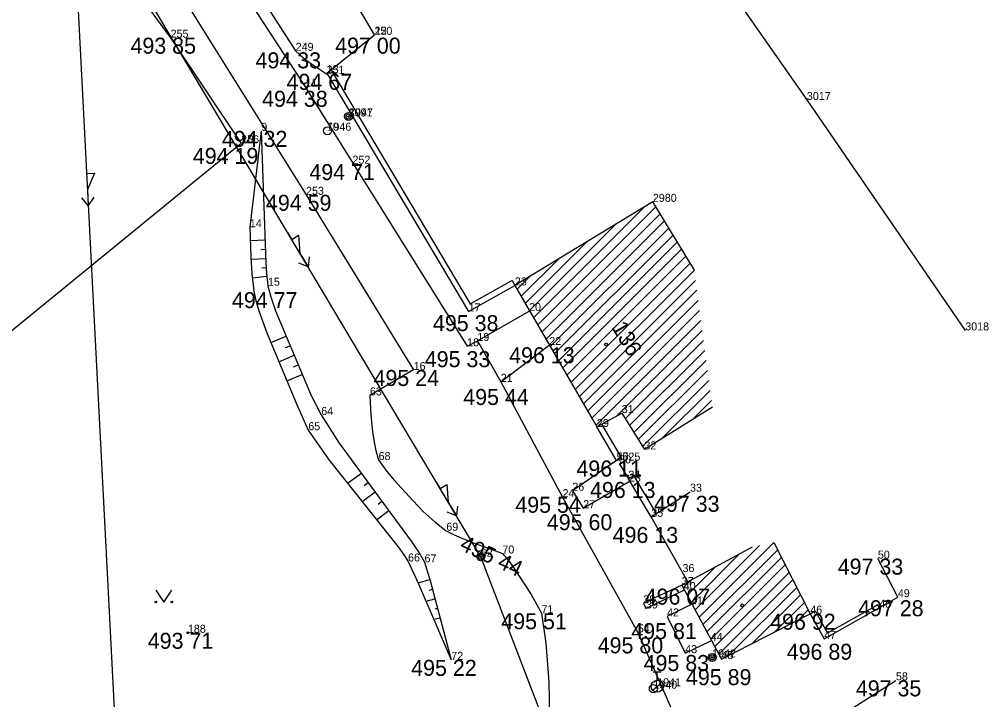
# Model space of a CAD drawing. Extents: x -559180 to -551373, y -1076947 to -1072071.
# Drawn here: x -553435.4 to -553374.8, y -1076636.3 to -1076593.8 of the extents above; entities that cross this region are included whole.
import ezdxf

# ---------------------------------------------------------------- set-up
doc = ezdxf.new("R2010")
doc.units = 0
for name, color, linetype in [('12_PLOTY', 7, 'Continuous'), ('14_BUDOVY', 7, 'Continuous'), ('17_KOMUNIKACE', 7, 'Continuous'), ('18_POLOHOPIS', 7, 'Continuous'), ('1_VODA_ZN', 7, 'Continuous'), ('20_EL_ZN', 7, 'Continuous'), ('26_SRAFY', 7, 'Continuous'), ('27_HRANA_PATA', 7, 'Continuous'), ('32', 7, 'Continuous'), ('3_BODY', 7, 'Continuous'), ('45_ZN_KULTURY', 7, 'Continuous'), ('47_ZN_STAV_OBJ$', 7, 'Continuous'), ('54_C_POPISNA', 7, 'Continuous'), ('6_VYSKY', 7, 'Continuous'), ('NNnadzemní', 7, 'Continuous')]:
    doc.layers.add(name, color=color, linetype=linetype)

# ---------------------------------------------------------------- blocks, each defined once
blk = doc.blocks.new('POINT_DISPLAY')
blk.add_line((0, 0), (0, 0))
blk = doc.blocks.new('SLB')
at = {"layer": '20_EL_ZN'}
for radius in [0.25, 0.158, 0.05]:
    blk.add_circle((0, 0), radius, dxfattribs=at)
blk = doc.blocks.new('BZ')
at = {"layer": '47_ZN_STAV_OBJ$'}
blk.add_circle((0, 0), 0.0875, dxfattribs=at)
blk = doc.blocks.new('PARK')
at = {"layer": '45_ZN_KULTURY'}
for p, q in [((-0.5, 0.75), (0, 0)), ((0, 0), (0.5, 0.75))]:
    blk.add_line(p, q, dxfattribs=at)
for centre in [(-0.5, 0), (0.5, 0)]:
    blk.add_circle(centre, 0.05, dxfattribs=at)
blk = doc.blocks.new('T')
at = {"layer": '6_VYSKY'}
blk.add_circle((0, 0), 0.05, dxfattribs=at)
blk = doc.blocks.new('SV')
at = {"layer": '1_VODA_ZN'}
blk.add_circle((0, 0), 0.25, dxfattribs=at)
blk = doc.blocks.new('OSV')
at = {"layer": '1_VODA_ZN'}
for radius in [0.25, 0.158, 0.05]:
    blk.add_circle((0, 0), radius, dxfattribs=at)
blk = doc.blocks.new('HYP')
at = {"layer": '1_VODA_ZN'}
for p, q in [((-0.25, 0.9), (0.25, 0.9)), ((0, 0.375), (0, 0.9)), ((-0.265, -0.265), (0.265, 0.265))]:
    blk.add_line(p, q, dxfattribs=at)
blk.add_circle((0, 0), 0.375, dxfattribs=at)
blk = doc.blocks.new('ELNN')
at = {"layer": '20_EL_ZN'}
for p, q in [((0, 0), (0.5, 0)), ((0.5, 0), (0.5, 0.5)), ((0.5, 0.5), (1.5, 0)), ((1.5, 0), (2.5, 0))]:
    blk.add_line(p, q, dxfattribs=at)
blk.add_lwpolyline([(2, 0.375), (2.5, 0), (2, -0.375)], dxfattribs=at)

msp = doc.modelspace()

# ---------------------------------------------------------------- linework, layer by layer
at = {"layer": '12_PLOTY'}
for p, q in [((-553413.2, -1076594.75), (-553428.34, -1076568.96)), ((-553397.99, -1076581.92), (-553386.19, -1076598.82)), ((-553428.08, -1076592), (-553425.93, -1076594.93)), ((-553425.93, -1076594.93), (-553421.52, -1076601.53)), ((-553416.18, -1076597.14), (-553413.2, -1076594.75)), ((-553407.193, -1076611.547), (-553415.904, -1076596.918)), ((-553416.18, -1076597.14), (-553407.32, -1076612.02)), ((-553386.19, -1076598.82), (-553376.3, -1076613.21)), ((-553421.52, -1076601.53), (-553438.11, -1076615.08)), ((-553407.32, -1076612.02), (-553404.43, -1076610.4)), ((-553404.601, -1076610.094), (-553407.193, -1076611.547)), ((-553404.601, -1076610.094), (-553404.43, -1076610.4)), ((-553398.08, -1076621.33), (-553399.3, -1076619.24)), ((-553397.777, -1076621.153), (-553398.997, -1076619.063)), ((-553398.08, -1076621.33), (-553397.777, -1076621.153)), ((-553397.91, -1076621.51), (-553397.34, -1076622.47)), ((-553397.34, -1076622.47), (-553396.997, -1076622.263)), ((-553395.91, -1076624.85), (-553397.34, -1076622.47)), ((-553395.574, -1076624.632), (-553396.997, -1076622.263)), ((-553395.91, -1076624.85), (-553393.49, -1076623.28)), ((-553393.621, -1076628.9), (-553395.91, -1076624.85)), ((-553380.51, -1076629.87), (-553381.76, -1076627.46)), ((-553381.768, -1076630.355), (-553384.902, -1076632.122)), ((-553381.67, -1076630.53), (-553381.768, -1076630.355)), ((-553381.67, -1076630.53), (-553380.51, -1076629.87)), ((-553385.98, -1076630.9), (-553385.673, -1076630.73)), ((-553385.98, -1076630.9), (-553385.11, -1076632.47)), ((-553385.673, -1076630.73), (-553384.902, -1076632.122)), ((-553385.11, -1076632.47), (-553381.67, -1076630.53))]:
    msp.add_line(p, q, dxfattribs=at)
at = {"layer": '14_BUDOVY'}
for p, q in [((-553395.81, -1076605.18), (-553404.43, -1076610.4)), ((-553393.22, -1076609.457), (-553395.81, -1076605.18)), ((-553404.43, -1076610.4), (-553399.3, -1076619.24)), ((-553392.093, -1076618.002), (-553396.34, -1076620.64)), ((-553399.3, -1076619.24), (-553397.75, -1076618.37)), ((-553397.75, -1076618.37), (-553396.34, -1076620.64)), ((-553389.609, -1076626.738), (-553394.01, -1076629.11)), ((-553388.255, -1076626.447), (-553385.98, -1076630.9)), ((-553394.01, -1076629.11), (-553391.52, -1076633.73)), ((-553391.52, -1076633.73), (-553385.98, -1076630.9))]:
    msp.add_line(p, q, dxfattribs=at)
at = {"layer": '17_KOMUNIKACE'}
for p, q in [((-553428.17, -1076581.72), (-553417.52, -1076597.99)), ((-553430.75, -1076583.45), (-553417.47, -1076604.74)), ((-553417.52, -1076597.99), (-553407.41, -1076614.2)), ((-553417.47, -1076604.74), (-553410.75, -1076615.68)), ((-553407.41, -1076614.2), (-553406.77, -1076613.87)), ((-553410.75, -1076615.68), (-553413.48, -1076617.27)), ((-553405.31, -1076616.42), (-553401.45, -1076623.62)), ((-553398.08, -1076621.34), (-553400.84, -1076623.22)), ((-553400.16, -1076624.31), (-553397.3, -1076622.65)), ((-553401.45, -1076623.62), (-553396.75, -1076632.07)), ((-553400.84, -1076623.22), (-553400.16, -1076624.31)), ((-553396.75, -1076632.07), (-553393.1, -1076640.32)), ((-553387.89, -1076639.66), (-553380.63, -1076635.06))]:
    msp.add_line(p, q, dxfattribs=at)
for points in [[(-553413.48, -1076617.27), (-553413.422, -1076618.481), (-553413.312, -1076619.549), (-553413.24, -1076620.071), (-553413.127, -1076620.625), (-553413.045, -1076620.945), (-553412.94, -1076621.3)], [(-553412.94, -1076621.3), (-553412.495, -1076621.933), (-553411.99, -1076622.542), (-553410.788, -1076623.858), (-553410.154, -1076624.515), (-553409.404, -1076625.19), (-553408.71, -1076625.72)], [(-553408.71, -1076625.72), (-553408.261, -1076625.962), (-553407.734, -1076626.179), (-553406.798, -1076626.565), (-553405.915, -1076626.869), (-553405.21, -1076627.14)], [(-553405.21, -1076627.14), (-553404.93, -1076627.452), (-553404.608, -1076627.895), (-553403.42, -1076629.704), (-553402.77, -1076630.87)], [(-553402.77, -1076630.87), (-553402.499, -1076632.736), (-553402.307, -1076635.159), (-553402.262, -1076637.403), (-553402.299, -1076638.629), (-553402.4, -1076639.7)]]:
    msp.add_lwpolyline(points, dxfattribs=at)
at = {"layer": '18_POLOHOPIS'}
for p, q in [((-553406.77, -1076613.87), (-553403.54, -1076612)), ((-553406.77, -1076613.87), (-553405.31, -1076616.42)), ((-553405.31, -1076616.42), (-553402.28, -1076614.12)), ((-553394.01, -1076629.11), (-553396.4, -1076630.25)), ((-553396.24, -1076630.57), (-553393.88, -1076629.42)), ((-553396.4, -1076630.25), (-553396.24, -1076630.57)), ((-553393.42, -1076630.32), (-553394.92, -1076631.07)), ((-553394.92, -1076631.07), (-553393.79, -1076633.36)), ((-553393.79, -1076633.36), (-553392.2, -1076632.6))]:
    msp.add_line(p, q, dxfattribs=at)
at = {"layer": '26_SRAFY'}
for p, q in [((-553420.957, -1076607.588), (-553420.034, -1076607.556)), ((-553420.287, -1076608.15), (-553420.014, -1076608.14)), ((-553420.893, -1076608.755), (-553419.994, -1076608.724)), ((-553420.829, -1076609.922), (-553419.92, -1076609.817)), ((-553420.234, -1076609.297), (-553419.965, -1076609.278)), ((-553419.664, -1076613.966), (-553418.716, -1076613.565)), ((-553418.749, -1076614.283), (-553418.464, -1076614.162)), ((-553419.166, -1076615.163), (-553418.211, -1076614.759)), ((-553418.246, -1076615.478), (-553417.959, -1076615.356)), ((-553418.669, -1076616.36), (-553417.706, -1076615.953)), ((-553414.875, -1076622.753), (-553414.017, -1076622.124)), ((-553413.839, -1076622.893), (-553413.588, -1076622.709)), ((-553413.972, -1076623.89), (-553413.159, -1076623.294)), ((-553412.968, -1076624.053), (-553412.73, -1076623.879)), ((-553413.07, -1076625.027), (-553412.301, -1076624.464)), ((-553410.469, -1076628.979), (-553409.747, -1076628.762)), ((-553409.772, -1076629.426), (-553409.579, -1076629.374)), ((-553409.979, -1076630.114), (-553409.421, -1076629.965)), ((-553409.404, -1076630.594), (-553409.263, -1076630.556)), ((-553409.49, -1076631.25), (-553409.104, -1076631.147))]:
    msp.add_line(p, q, dxfattribs=at)
at = {"layer": '27_HRANA_PATA'}
for p, q in [((-553431.6, -1076574.87), (-553418.12, -1076595.75)), ((-553420.27, -1076600.75), (-553420.98, -1076606.77))]:
    msp.add_line(p, q, dxfattribs=at)
for points in [[(-553418.12, -1076595.75), (-553417.649, -1076596.188), (-553417.189, -1076596.53), (-553416.129, -1076597.225)], [(-553420.27, -1076600.75), (-553419.985, -1076608.979), (-553419.941, -1076609.633), (-553419.85, -1076610.42)], [(-553420.98, -1076606.77), (-553420.927, -1076608.629), (-553420.861, -1076609.662), (-553420.734, -1076610.754), (-553420.624, -1076611.267), (-553420.423, -1076611.987), (-553419.918, -1076613.354), (-553418.069, -1076617.804), (-553417.33, -1076619.44)], [(-553419.85, -1076610.42), (-553419.673, -1076611.118), (-553419.384, -1076611.987), (-553417.149, -1076617.269), (-553416.52, -1076618.49)], [(-553416.52, -1076618.49), (-553415.397, -1076620.241), (-553410.906, -1076626.368), (-553410.416, -1076627.096), (-553410.07, -1076627.69)], [(-553417.33, -1076619.44), (-553416.021, -1076621.31), (-553411.722, -1076626.725), (-553411.366, -1076627.23), (-553411.1, -1076627.64)], [(-553411.1, -1076627.64), (-553410.446, -1076629.028), (-553408.4, -1076633.78)], [(-553410.07, -1076627.69), (-553409.703, -1076628.909), (-553408.4, -1076633.78)]]:
    msp.add_lwpolyline(points, dxfattribs=at)
at = {"layer": '32'}
for p, q in [((-553403.256, -1076612.422), (-553396.327, -1076605.493)), ((-553402.997, -1076612.87), (-553395.62, -1076605.493)), ((-553402.737, -1076613.317), (-553395.354, -1076605.934)), ((-553403.516, -1076611.975), (-553398.12, -1076606.579)), ((-553402.477, -1076613.765), (-553395.087, -1076606.374)), ((-553402.218, -1076614.212), (-553394.82, -1076606.815)), ((-553401.958, -1076614.66), (-553394.553, -1076607.255)), ((-553403.776, -1076611.527), (-553399.913, -1076607.665)), ((-553401.698, -1076615.107), (-553394.287, -1076607.695)), ((-553401.439, -1076615.554), (-553394.02, -1076608.136)), ((-553401.179, -1076616.002), (-553393.753, -1076608.576)), ((-553404.035, -1076611.08), (-553401.706, -1076608.75)), ((-553400.919, -1076616.449), (-553393.487, -1076609.017)), ((-553400.66, -1076616.897), (-553393.22, -1076609.457)), ((-553404.295, -1076610.633), (-553403.498, -1076609.836)), ((-553400.4, -1076617.344), (-553393.138, -1076610.082)), ((-553400.14, -1076617.792), (-553393.055, -1076610.706)), ((-553399.881, -1076618.239), (-553392.973, -1076611.331)), ((-553399.621, -1076618.687), (-553392.89, -1076611.956)), ((-553399.361, -1076619.134), (-553392.808, -1076612.581)), ((-553398.07, -1076618.55), (-553392.726, -1076613.205)), ((-553397.533, -1076618.72), (-553392.643, -1076613.83)), ((-553397.262, -1076619.156), (-553392.561, -1076614.455)), ((-553396.991, -1076619.592), (-553392.478, -1076615.079)), ((-553396.72, -1076620.028), (-553392.396, -1076615.704)), ((-553396.449, -1076620.464), (-553392.314, -1076616.329)), ((-553395.225, -1076619.948), (-553392.231, -1076616.954)), ((-553393.359, -1076618.788), (-553392.149, -1076617.578)), ((-553393.175, -1076630.66), (-553389.156, -1076626.641)), ((-553392.927, -1076631.119), (-553388.255, -1076626.447)), ((-553393.422, -1076630.2), (-553390.371, -1076627.149)), ((-553392.68, -1076631.579), (-553388.016, -1076626.915)), ((-553392.432, -1076632.038), (-553387.777, -1076627.383)), ((-553393.67, -1076629.741), (-553391.905, -1076627.975)), ((-553392.184, -1076632.498), (-553387.538, -1076627.851)), ((-553391.937, -1076632.957), (-553387.299, -1076628.319)), ((-553393.918, -1076629.281), (-553393.438, -1076628.802)), ((-553391.689, -1076633.416), (-553387.059, -1076628.787)), ((-553391.061, -1076633.495), (-553386.82, -1076629.255)), ((-553389.615, -1076632.757), (-553386.581, -1076629.723)), ((-553388.17, -1076632.019), (-553386.342, -1076630.191)), ((-553386.724, -1076631.28), (-553386.103, -1076630.659))]:
    msp.add_line(p, q, dxfattribs=at)
at = {"layer": 'NNnadzemní'}
for p, q in [((-553406.56, -1076627.34), (-553432.16, -1076584.36)), ((-553432.16, -1076584.36), (-553429.16, -1076642.36)), ((-553396.48, -1076653.54), (-553406.56, -1076627.34))]:
    msp.add_line(p, q, dxfattribs=at)

# ---------------------------------------------------------------- block references
at = {"layer": '12_PLOTY'}
msp.add_blockref('POINT_DISPLAY', (-553397.34, -1076622.47), dxfattribs=at)
at = {"layer": '1_VODA_ZN'}
for name, p in [('POINT_DISPLAY', (-553425.93, -1076594.93)), ('POINT_DISPLAY', (-553413.2, -1076594.75)), ('POINT_DISPLAY', (-553413.17, -1076594.74)), ('POINT_DISPLAY', (-553418.12, -1076595.75)), ('POINT_DISPLAY', (-553416.19, -1076597.18)), ('POINT_DISPLAY', (-553416.18, -1076597.14)), ('POINT_DISPLAY', (-553417.52, -1076597.99)), ('POINT_DISPLAY', (-553386.19, -1076598.82)), ('OSV', (-553414.81, -1076599.85)), ('POINT_DISPLAY', (-553414.81, -1076599.85)), ('POINT_DISPLAY', (-553414.78, -1076599.84)), ('POINT_DISPLAY', (-553420.27, -1076600.75)), ('SV', (-553416.13, -1076600.74)), ('POINT_DISPLAY', (-553416.17, -1076600.73)), ('POINT_DISPLAY', (-553416.13, -1076600.74)), ('POINT_DISPLAY', (-553421.52, -1076601.53)), ('POINT_DISPLAY', (-553421.5, -1076601.48)), ('POINT_DISPLAY', (-553414.57, -1076602.8)), ('POINT_DISPLAY', (-553417.47, -1076604.74)), ('POINT_DISPLAY', (-553395.81, -1076605.18)), ('POINT_DISPLAY', (-553420.98, -1076606.77)), ('POINT_DISPLAY', (-553419.85, -1076610.42)), ('POINT_DISPLAY', (-553404.43, -1076610.4)), ('POINT_DISPLAY', (-553407.32, -1076612.02)), ('POINT_DISPLAY', (-553403.54, -1076612)), ('POINT_DISPLAY', (-553376.3, -1076613.21)), ('POINT_DISPLAY', (-553406.77, -1076613.87)), ('POINT_DISPLAY', (-553407.41, -1076614.2)), ('POINT_DISPLAY', (-553402.28, -1076614.12)), ('POINT_DISPLAY', (-553410.75, -1076615.68)), ('POINT_DISPLAY', (-553405.31, -1076616.42)), ('POINT_DISPLAY', (-553413.48, -1076617.27)), ('POINT_DISPLAY', (-553416.52, -1076618.49)), ('POINT_DISPLAY', (-553397.75, -1076618.37)), ('POINT_DISPLAY', (-553417.33, -1076619.44)), ('POINT_DISPLAY', (-553399.3, -1076619.24)), ('POINT_DISPLAY', (-553396.34, -1076620.64)), ('POINT_DISPLAY', (-553412.94, -1076621.3)), ('POINT_DISPLAY', (-553398.08, -1076621.33)), ('POINT_DISPLAY', (-553398.08, -1076621.34)), ('POINT_DISPLAY', (-553397.91, -1076621.51)), ('POINT_DISPLAY', (-553397.34, -1076622.47)), ('POINT_DISPLAY', (-553397.3, -1076622.65)), ('POINT_DISPLAY', (-553401.45, -1076623.62)), ('POINT_DISPLAY', (-553400.84, -1076623.22)), ('POINT_DISPLAY', (-553393.49, -1076623.28)), ('POINT_DISPLAY', (-553400.16, -1076624.31)), ('POINT_DISPLAY', (-553395.91, -1076624.85)), ('POINT_DISPLAY', (-553408.71, -1076625.72)), ('POINT_DISPLAY', (-553406.56, -1076627.34)), ('POINT_DISPLAY', (-553405.21, -1076627.14)), ('POINT_DISPLAY', (-553411.1, -1076627.64)), ('POINT_DISPLAY', (-553410.07, -1076627.69)), ('POINT_DISPLAY', (-553381.76, -1076627.46)), ('POINT_DISPLAY', (-553393.96, -1076628.3)), ('POINT_DISPLAY', (-553394.01, -1076629.11)), ('POINT_DISPLAY', (-553393.88, -1076629.42)), ('POINT_DISPLAY', (-553396.4, -1076630.25)), ('POINT_DISPLAY', (-553393.42, -1076630.32)), ('POINT_DISPLAY', (-553380.51, -1076629.87)), ('POINT_DISPLAY', (-553402.77, -1076630.87)), ('POINT_DISPLAY', (-553396.24, -1076630.57)), ('POINT_DISPLAY', (-553385.98, -1076630.9)), ('POINT_DISPLAY', (-553381.67, -1076630.53)), ('POINT_DISPLAY', (-553394.92, -1076631.07)), ('POINT_DISPLAY', (-553424.85, -1076632.09)), ('POINT_DISPLAY', (-553396.75, -1076632.07)), ('POINT_DISPLAY', (-553392.2, -1076632.6)), ('POINT_DISPLAY', (-553385.11, -1076632.47)), ('POINT_DISPLAY', (-553393.79, -1076633.36)), ('OSV', (-553392.11, -1076633.63)), ('POINT_DISPLAY', (-553408.4, -1076633.78)), ('POINT_DISPLAY', (-553392.11, -1076633.63)), ('POINT_DISPLAY', (-553391.52, -1076633.73)), ('HYP', (-553395.54, -1076635.43)), ('POINT_DISPLAY', (-553380.63, -1076635.06)), ('SV', (-553395.78, -1076635.58)), ('POINT_DISPLAY', (-553395.78, -1076635.58)), ('POINT_DISPLAY', (-553395.54, -1076635.43))]:
    msp.add_blockref(name, p, dxfattribs=at)
at = {"layer": '20_EL_ZN'}
for p, xscale, yscale, rotation in [((-553431.2, -1076602.916), 0.9999986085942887, 0.9999986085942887, -87.03901333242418), ((-553418.619, -1076607.094), 1.000000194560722, 1.000000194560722, -59.22087175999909), ((-553409.354, -1076622.649), 1.000000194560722, 1.000000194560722, -59.22087175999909)]:
    msp.add_blockref('ELNN', p, dxfattribs=dict(at, xscale=xscale, yscale=yscale, rotation=rotation))
msp.add_blockref('SLB', (-553406.56, -1076627.34), dxfattribs=at)
at = {"layer": '32'}
for p in [(-553393.22, -1076609.457), (-553388.255, -1076626.447)]:
    msp.add_blockref('POINT_DISPLAY', p, dxfattribs=at)
at = {"layer": '45_ZN_KULTURY'}
msp.add_blockref('PARK', (-553426.354, -1076630.172), dxfattribs=at)
at = {"layer": '47_ZN_STAV_OBJ$'}
for p in [(-553398.727, -1076614.086), (-553390.23, -1076630.377)]:
    msp.add_blockref('BZ', p, dxfattribs=at)
at = {"layer": '6_VYSKY'}
msp.add_blockref('T', (-553424.85, -1076632.09), dxfattribs=at)
msp.add_blockref('T', (-553424.85, -1076632.09), dxfattribs=at)

# ---------------------------------------------------------------- texts
at = {"layer": '3_BODY'}
for s, p in [('255', (-553425.93, -1076594.93)), ('250', (-553413.2, -1076594.75)), ('12', (-553413.17, -1076594.74)), ('249', (-553418.12, -1076595.75)), ('251', (-553416.19, -1076597.18)), ('13', (-553416.18, -1076597.14)), ('11', (-553417.52, -1076597.99)), ('3017', (-553386.19, -1076598.82)), ('3091', (-553414.81, -1076599.85)), ('1947', (-553414.78, -1076599.84)), ('9', (-553420.27, -1076600.75)), ('70', (-553416.17, -1076600.73)), ('1946', (-553416.13, -1076600.74)), ('256', (-553421.52, -1076601.53)), ('10', (-553421.5, -1076601.48)), ('252', (-553414.57, -1076602.8)), ('253', (-553417.47, -1076604.74)), ('2980', (-553395.81, -1076605.18)), ('14', (-553420.98, -1076606.77)), ('15', (-553419.85, -1076610.42)), ('23', (-553404.43, -1076610.4)), ('17', (-553407.32, -1076612.02)), ('20', (-553403.54, -1076612)), ('3018', (-553376.3, -1076613.21)), ('19', (-553406.77, -1076613.87)), ('18', (-553407.41, -1076614.2)), ('22', (-553402.28, -1076614.12)), ('16', (-553410.75, -1076615.68)), ('21', (-553405.31, -1076616.42)), ('63', (-553413.48, -1076617.27)), ('64', (-553416.52, -1076618.49)), ('31', (-553397.75, -1076618.37)), ('29', (-553399.3, -1076619.24)), ('65', (-553417.33, -1076619.44)), ('32', (-553396.34, -1076620.64)), ('68', (-553412.94, -1076621.3)), ('5025', (-553398.08, -1076621.34)), ('25', (-553398.08, -1076621.33)), ('30', (-553397.91, -1076621.51)), ('34', (-553397.34, -1076622.47)), ('28', (-553397.3, -1076622.65)), ('24', (-553401.45, -1076623.62)), ('26', (-553400.84, -1076623.22)), ('33', (-553393.49, -1076623.28)), ('27', (-553400.16, -1076624.31)), ('35', (-553395.91, -1076624.85)), ('69', (-553408.71, -1076625.72)), ('70', (-553405.21, -1076627.14)), ('66', (-553411.1, -1076627.64)), ('67', (-553410.07, -1076627.69)), ('62', (-553406.56, -1076627.34)), ('50', (-553381.76, -1076627.46)), ('36', (-553393.96, -1076628.3)), ('37', (-553394.01, -1076629.11)), ('40', (-553393.88, -1076629.42)), ('38', (-553396.4, -1076630.25)), ('49', (-553380.51, -1076629.87)), ('71', (-553402.77, -1076630.87)), ('39', (-553396.24, -1076630.57)), ('41', (-553393.42, -1076630.32)), ('46', (-553385.98, -1076630.9)), ('48', (-553381.67, -1076630.53)), ('42', (-553394.92, -1076631.07)), ('188', (-553424.85, -1076632.09)), ('54', (-553396.75, -1076632.07)), ('44', (-553392.2, -1076632.6)), ('47', (-553385.11, -1076632.47)), ('72', (-553408.4, -1076633.78)), ('43', (-553393.79, -1076633.36)), ('1942', (-553392.11, -1076633.63)), ('45', (-553391.52, -1076633.73)), ('58', (-553380.63, -1076635.06)), ('1940', (-553395.78, -1076635.58)), ('1941', (-553395.54, -1076635.43))]:
    msp.add_text(s, height=0.5, dxfattribs=at).set_placement(p)
at = {"layer": '54_C_POPISNA'}
msp.add_text('136', height=1, rotation=300.12731, dxfattribs=at).set_placement((-553398.417, -1076612.993))
at = {"layer": '6_VYSKY'}
for s, p in [('493 85', (-553428.435, -1076595.93)), ('497 00', (-553415.652, -1076595.927)), ('494 33', (-553420.625, -1076596.844)), ('494 67', (-553418.685, -1076598.187)), ('494 38', (-553420.212, -1076599.247)), ('494 32', (-553422.728, -1076601.75)), ('494 19', (-553424.54, -1076602.811)), ('494 71', (-553417.262, -1076603.824)), ('494 59', (-553419.975, -1076605.74)), ('494 77', (-553422.098, -1076611.818)), ('495 38', (-553409.544, -1076613.254)), ('495 33', (-553410.055, -1076615.504)), ('496 13', (-553404.785, -1076615.26)), ('495 24', (-553413.255, -1076616.68)), ('495 44', (-553407.651, -1076617.865)), ('496 11', (-553400.585, -1076622.33)), ('496 11', (-553400.585, -1076622.34)), ('496 13', (-553399.734, -1076623.674)), ('495 54', (-553404.4, -1076624.597)), ('497 33', (-553395.738, -1076624.537)), ('495 60', (-553402.431, -1076625.685)), ('496 13', (-553398.322, -1076626.482)), ('497 33', (-553384.265, -1076628.46)), ('496 07', (-553396.32, -1076630.334)), ('497 28', (-553382.992, -1076631.057)), ('495 51', (-553405.275, -1076631.87)), ('496 92', (-553388.485, -1076631.9)), ('495 81', (-553397.155, -1076632.486)), ('493 71', (-553427.355, -1076633.09)), ('495 80', (-553399.255, -1076633.374)), ('496 89', (-553387.451, -1076633.774)), ('495 22', (-553410.905, -1076634.78)), ('495 83', (-553396.389, -1076634.477)), ('495 89', (-553393.744, -1076635.361)), ('497 35', (-553383.135, -1076636.06))]:
    msp.add_text(s, height=1, dxfattribs=at).set_placement(p)
msp.add_text('495 44', height=1, rotation=334.58175, dxfattribs=at).set_placement((-553407.94, -1076626.866))

doc.saveas('drawing.dxf')
